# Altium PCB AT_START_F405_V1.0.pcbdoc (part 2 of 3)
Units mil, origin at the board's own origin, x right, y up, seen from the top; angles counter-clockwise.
Board outline 15424.54 x 3535.36 mil, 2 copper layers (Top Layer, Bottom Layer); 147 components, 139 nets, 556 pads, 794 vias.
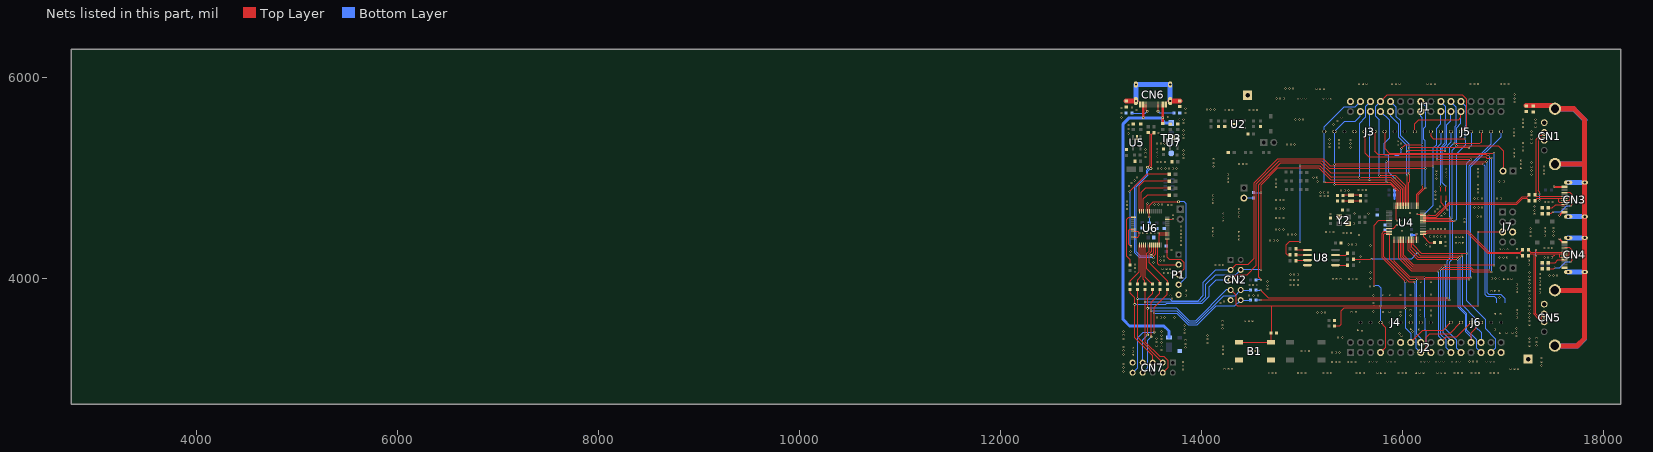
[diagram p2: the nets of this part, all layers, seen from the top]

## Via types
v1: diameter 19.68, hole 11.81, Top Layer to Bottom Layer, 688 vias
v2: diameter 19.69, hole 11.81, Top Layer to Bottom Layer, 42 vias
v3: diameter 19.7, hole 11.81, Top Layer to Bottom Layer, 30 vias
v4: diameter 23.62, hole 11.81, Top Layer to Bottom Layer, 17 vias
v5: diameter 27.56, hole 13.78, Top Layer to Bottom Layer, 15 vias
v6: diameter 27.56, hole 15.75, Top Layer to Bottom Layer, 2 vias

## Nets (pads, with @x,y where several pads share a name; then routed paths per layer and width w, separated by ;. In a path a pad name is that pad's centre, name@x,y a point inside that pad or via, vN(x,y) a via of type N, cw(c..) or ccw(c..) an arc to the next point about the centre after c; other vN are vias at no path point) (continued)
$4N333: C24.2 R23.2 Y1.2 | length 173.4
  Top Layer w6: C24.2@15411.08,4772.56 15412.08,4773.56 R23.2@15584.08,4773.56
$4N335: C23.2 R22.2 Y1.1 | length 171
  Top Layer w6: C23.2@15411.08,4831.56 Y1.1@15487.58,4831.56 R22.2@15582.08,4831.56
$4N462: JP1.2 R31.1 | length 95.9
  Bottom Layer w6: JP1.2@14423.65,4803.5 R31.1@14519.52,4803.5
ATLINK_5V: CN6.A4B9 CN6.B4A9 D3.2 F2.1 TP3.1 | length 3381.4
  Top Layer w25: v5(13421.92,5603.02) 13422.08,5603.17 CN6.B4A9@13422.08,5734.27 ; v5(13614.56,5603.02) v5@13615.03,5603.49 ; CN6.A4B9@13615.08,5734.27 13615.08,5603.49 13615.08,5548.73 F2.1@13616.58,5547.23
  Bottom Layer w30: D3.2@13676.62,3414.32 13676.58,3481.57 13626.58,3531.57 13283.81,3531.57 13220.92,3594.45 13220.92,5542.59 13281.34,5603.02 v5(13421.92,5603.02) v5(13614.56,5603.02) 13614.56,5572.39 13636.92,5550.02 TP3.1@13699.92,5550.02
ATLK_RX: CN2.10 CN7.10 R10.2 R48.1 | length 2143.2
  Top Layer w6: v4(13530.58,3469.57) v2(13530.58,3659.57) 13530.58,3717.57 13660.58,3847.57 R48.1@13660.58,3892.07
  Bottom Layer w6: CN7.10@13315.34,3066.01 13365.92,3116.59 13365.92,3415.01 13420.47,3469.57 v4(13530.58,3469.57) ; v2(13530.58,3659.57) 13752.58,3659.57 13868.58,3543.57 13960.58,3543.57 14148.58,3731.57 14333.65,3731.57 CN2.10@14390.92,3788.84 ; CN2.10@14390.97,3788.89 14391.26,3789.2 R10.2@14490.52,3789.2
ATLK_TX: CN2.8 CN7.8 R9.2 R47.1 | length 2063.7
  Top Layer w6: v4(13499.34,3422.01) 13499.34,3768.34 13586.34,3855.34 R47.1@13586.34,3885.01
  Bottom Layer w6: CN7.8@13415.35,3066.01 13463.92,3114.58 13463.92,3386.58 v4(13499.34,3422.01) ; v4(13498.58,3681.57) 13756.58,3681.57 13876.58,3561.57 13950.58,3561.57 14222.58,3833.57 14335.65,3833.57 CN2.8@14390.92,3888.84 14392.02,3887.74 R9.2@14486.73,3887.74
BOOT0/PF11: CN2.4 CN7.4 J1.28 R31.2 R45.1 U4.60 | length 5639.3
  Top Layer w6: R45.1@13438.34,3887.01 13438.34,3375.8 13583.12,3231.01 13623.92,3231.01 13665.92,3189.01 13665.92,3116.59 CN7.4@13615.34,3066.01 ; v2@14594.52,4089.62 v3(14594.52,4858.5) 14594.52,4937.51 14760.58,5103.56 15169.95,5103.56 15287.95,4985.56 v1(15675.45,4985.56) 15884.58,4985.56 15982.45,4887.69 U4.60@15982.45,4727.85
  Bottom Layer w6: v4(13438.58,3769.57) 13994.58,3769.57 14044.58,3819.57 14044.58,3944.57 14141.58,4041.57 14343.65,4041.57 CN2.4@14390.92,4088.84 14391.65,4089.57 v2(14594.58,4089.57) ; R31.2@14513.52,4858.5 v3(14594.52,4858.5) ; v1(15675.45,4985.56) 15675.58,4985.82 15675.58,5656.99 J1.28@15683.44,5664.86
CC1: CN6.A5 R56.1 | length 231.5
  Top Layer w6: v5@13567.58,5668.56 v5(13567.77,5668.77) CN6.A5@13567.77,5734.27
  Bottom Layer w6: v5(13567.77,5668.77) 13585.98,5650.56 R56.1@13725.92,5650.56
CC2: CN6.B5 R57.1 | length 230.4
  Top Layer w6: CN6.B5@13449.67,5734.27 13449.67,5680.47 v5(13461.58,5668.56)
  Bottom Layer w6: R57.1@13309.24,5650.56 13443.58,5650.56 v5(13461.58,5668.56)
CS: R60.2 U8.1 | length 119.5
  Top Layer w6: R60.2@14941.52,4299 14953.52,4287 U8.1@15056.06,4287
EGND: C30.2 CN1.SH1 CN1.SH2 CN3.13 CN3.14 CN3.15 CN3.16 CN4.13 CN4.14 CN4.15 CN4.16 CN5.SH1 CN5.SH2 R59.1 | length 7841
  Top Layer w50: C30.2@17233.58,5723.56 17489.51,5723.56 CN1.SH1@17519.93,5693.15 17706.99,5693.15 17815.88,5584.27 17815.88,5146.56 ; CN5.SH2@17518.93,3334.97 17522.33,3331.57 17738.58,3331.57 17815.88,3408.86 17815.88,3885.08 ; CN5.SH1@17518.93,3886.15 17814.8,3886.15 17815.88,3885.08 ; CN1.SH2@17519.93,5141.97 17811.28,5141.97 17815.88,5146.56 ; 17815.88,3885.08 CN4.15@17815.88,4068.47 CN4.16@17815.88,4408.66 CN3.15@17815.88,4618.47 CN3.16@17815.88,4958.66 17815.88,5146.56
  Bottom Layer w50: CN5.SH2@17518.93,3334.97 17520.33,3333.57 17745.58,3333.57 17815.88,3403.86 17815.88,3884.97 ; CN5.SH1@17518.93,3886.15 17814.69,3886.15 17815.88,3884.97 ; CN1.SH2@17519.93,5141.97 17812.82,5141.97 17815.88,5138.92 ; CN1.SH1@17519.93,5693.15 17703.99,5693.15 17816.58,5580.56 17815.88,5579.86 17815.88,5138.92 ; CN4.13@17651.28,4068.47 CN4.15@17815.88,4068.47 ; CN4.14@17651.28,4408.66 CN4.16@17815.88,4408.66 ; CN3.13@17651.28,4618.47 CN3.15@17815.88,4618.47 ; CN3.14@17651.28,4958.66 CN3.16@17815.88,4958.66 ; 17815.88,3884.97 CN4.15@17815.88,4068.47 ; CN4.15@17815.88,4068.47 CN4.16@17815.88,4408.66 ; CN4.16@17815.88,4408.66 CN3.15@17815.88,4618.47 ; CN3.15@17815.88,4618.47 CN3.16@17815.88,4958.66 ; CN3.16@17815.88,4958.66 17815.88,5138.92
EGND2: C29.2 CN6.13 CN6.14 CN6.15 CN6.16 R55.1 | length 863.4
  Top Layer w50: R55.1@13250.58,5770.56 13348.17,5770.56 CN6.14@13348.48,5770.27 ; CN6.13@13688.67,5770.27 13688.82,5770.12 C29.2@13784.58,5770.12
  Bottom Layer w50: CN6.14@13348.48,5770.27 CN6.16@13348.48,5934.86 CN6.15@13688.67,5934.86 CN6.13@13688.67,5770.27
FCC1: CN3.A5 R17.1 | length 176.6
  Top Layer w6: R17.1@17452.24,4706.56 17494.58,4706.56 17527.38,4739.36 CN3.A5@17615.28,4739.36
FCC2: CN3.B5 R16.1 | length 457.9
  Top Layer w6: R16.1@17453.24,4646.56 17478.58,4646.56 v1(17499.58,4667.56) ; CN3.B5@17615.28,4857.47 17669.67,4857.47 17692.58,4834.56 17692.58,4742.56 v1(17675.58,4725.56)
  Bottom Layer w6: v1(17499.58,4667.56) 17576.58,4667.56 17634.58,4725.56 v1(17675.58,4725.56)
FD+: CN1.3 CN3.A6 CN3.B6 R18.2 | length 1102.9
  Top Layer w11.2: R18.2@17321.58,4833.56 R18.2@17321.4,4833.4 ; CN1.3@17413.22,5456.93 17382.46,5426.16 17369.73,5426.16 17334.38,5390.81 17334.38,4850.36 R18.2@17321.58,4837.56 17321.4,4837.4 R18.2@17321.4,4833.4 ; CN3.A6@17615.28,4778.77 17658.78,4778.77 17666.58,4786.56 17666.58,4809.56 17658.08,4818.06 CN3.B6@17615.28,4818.06 17579.12,4818.06 17577.88,4816.81 17337.99,4816.81 R18.2@17321.4,4833.4
FD-: CN1.2 CN3.A7 CN3.B7 R19.2 | length 1109.5
  Top Layer w11.2: R19.2@17321.24,4774.56 17321.24,4781.87 17338.98,4799.61 17367.52,4799.61 ; v1(17367.52,4779.62) 17367.52,4799.61 ; v1(17367.58,4843.56) 17367.58,4861.56 17351.58,4877.56 17351.58,5383.68 17369.16,5401.27 17390.15,5401.27 CN1.2@17413.22,5378.19 ; 17559.58,4799.5 17559.58,4767.56 17568.08,4759.06 CN3.B7@17615.28,4759.06 ; CN3.A7@17615.28,4798.36 17579.12,4798.36 17577.88,4799.61 17367.52,4799.61
  Bottom Layer w11.2: v1(17367.52,4779.62) v1@17367.52,4843.51
GND: B1.3 B1.4 C1.2 C2.2 C3.2 C4.2 C5.2 C6.2 C7.2 C8.2 C9.2 C10.2 C11.2 C12.2 C13.1 C14.2 C15.2 C16.2 C17.2 C18.2 C19.2 C20.1 C22.2 C23.1 C24.1 C25.1 C26.1 C27.1 C28.1 C29.1 C30.1 CN1.4 CN2.9 CN3.A1B12 CN3.B1A12 CN4.A1B12 CN4.B1A12 CN5.4 CN6.A1B12 CN6.B1A12 CN7.9 D4.2 J1.31 J2.12 J2.31 J3.7 J4.6 J4.7 J7.6 LED1.2 P1.5 R2.1 R7.2 R16.2 R17.2 R20.2 R40.2 R42.2 R49.2 R51.2 R55.2 R56.2 R57.2 R59.2 T1.1 T2.1 TP3.4 U2.2 U4.12 U4.31 U4.63 U5.2 U6.8 U6.20 U6.23 U6.35 U6.39 U6.40 U6.47 U7.2 U8.4 Y2.2 Y2.4 | length 1299.9
  Top Layer w6: v1(17488.04,4212.56) 17510.36,4234.88 17518.46,4234.89
  Top Layer w8: U4.12@15868.28,4503.44 15913.45,4503.44 v1(15946.58,4536.56) ; U4.63@15935.22,4727.85 15935.22,4593.93 v1(15946.58,4582.56) ; v1(16139.58,4445.56) 16139.93,4445.2 U4.31@16139.93,4389.27
  Top Layer w10: U6.23@13324.5,4416.1 13365.11,4416.1 13383.58,4434.56 v1(13383.58,4457.56) 13365.98,4475.16 U6.20@13324.5,4475.16 ; U6.8@13462.3,4672.02 13462.58,4672.3 v1(13462.58,4749.56) ; U6.35@13580.41,4337.36 13580.41,4448.2 ; U6.39@13659.15,4435.8 13592.81,4435.8 13580.41,4448.2 ; U6.40@13659.15,4455.48 13659.06,4455.56 v1(13573.04,4455.56) 13580.41,4448.2 ; U6.47@13659.15,4593.27 13717.28,4593.27 v1(13717.58,4593.56)
  Top Layer w20: v1(17508.58,4919.56) 17513.58,4914.56 17614.47,4914.56 CN3.B1A12@17615.28,4915.36 ; v1(17562.58,4398.56) 17595.78,4365.36 CN4.B1A12@17615.28,4365.36 ; v1(17564.58,4632.56) 17593.58,4661.56 CN3.A1B12@17615.28,4661.56
  Bottom Layer w20: C4.2@15924.08,4883.56 15924.58,4883.06 C5.2@15924.58,4833.56 15924.58,4796.56 ; C6.2@16091.58,4434.06 16128.08,4434.06 v1(16139.58,4445.56)
  other v1: 14670.58,3063.57 14707.81,3063.57 14745.04,3063.57 14960.58,3063.57 14997.81,3063.57 15035.04,3063.57 15217.58,3063.57 15254.81,3063.57 15292.04,3063.57 15542.58,3063.57 15579.81,3063.57 15617.04,3063.57 15962.58,3063.57 15999.81,3063.57 16037.04,3063.57 16518.58,3063.57 16555.81,3063.57 16593.04,3063.57 16689.58,3063.57 16726.81,3063.57 16764.04,3063.57 16876.58,3063.57 16913.81,3063.57 16951.04,3063.57 15752.58,3064.57 15789.81,3064.57 15827.04,3064.57 16134.58,3064.57 16171.81,3064.57 16209.04,3064.57 16350.58,3064.57 16387.81,3064.57 16425.04,3064.57 13225.58,3078.57 13817.58,3097.57 14230.58,3100.57 14267.81,3100.57 14305.04,3100.57 17077.58,3104.57 17114.81,3104.57 17152.04,3104.57 13225.58,3115.8 13817.58,3134.8 17387.58,3136.57 13225.58,3153.03 13817.58,3172.03 15300.58,3173.57 15337.81,3173.57 15375.04,3173.57 15457.58,3173.57 15494.81,3173.57 15532.04,3173.57 17387.58,3173.8 15666.58,3174.57 15703.81,3174.57 15741.04,3174.57 15851.58,3174.57 15888.81,3174.57 15926.04,3174.57 16185.58,3174.57 16222.81,3174.57 16260.04,3174.57 16334.58,3174.57 16371.81,3174.57 16409.04,3174.57 16495.58,3174.57 16532.81,3174.57 16570.04,3174.57 16838.58,3174.57 16875.81,3174.57 16913.04,3174.57 16667.58,3175.57 16704.81,3175.57 16742.04,3175.57 17387.58,3211.03 13317.58,3239.57 13224.58,3247.57 14213.58,3252.57 15300.58,3267.57 15337.81,3267.57 15375.04,3267.57 13317.58,3276.8 14494.29,3280.57 14531.52,3280.57 14568.75,3280.57 14996.57,3280.56 15033.8,3280.56 15071.04,3280.56 13224.58,3284.8 14213.58,3289.8 13601.58,3291.57 13317.58,3314.03 13840.58,3314.57 13224.58,3322.03 14213.58,3327.03 13601.58,3328.8 13553.58,3333.57 17268.58,3333.57 17336.58,3334.57 13840.58,3351.8 14059.58,3362.57 13601.58,3366.03 13553.58,3370.8 17268.58,3370.8 17336.58,3371.8 13840.58,3389.03 14059.58,3399.8 13601.58,3400.57 13224.58,3401.57 13553.58,3408.03 17268.58,3408.03 17336.58,3409.03 15360.58,3416.57 15406.97,3416.57 17138.58,3429.57 15992.58,3432.57 14059.58,3437.03 13601.58,3437.8 13224.58,3438.8 15971.58,3454.57 13829.58,3459.57 16974.58,3462.57 17036.92,3462.57 17098.36,3462.57 17138.58,3466.8 13601.58,3475.03 13224.58,3476.03 16100.58,3476.57 15597.58,3478.57 15560.58,3492.57 16920.58,3496.35 13829.58,3496.8 16168.58,3497.57 16088.58,3502.57 14210.58,3503.57 17138.58,3504.03 13829.58,3534.03 14210.58,3540.8 17268.58,3542.1 14210.58,3578.03 17268.58,3579.33 14436.58,3582.57 14473.81,3582.57 14511.04,3582.57 13559.11,3615.57 13596.34,3615.57 13633.58,3615.57 13731.58,3616.57 17139.58,3616.57 17268.58,3616.57 15981.58,3633.57 16285.58,3634.57 16081.58,3635.57 16178.58,3635.57 16920.58,3647.57 16975.48,3647.57 17139.58,3653.8 17267.58,3655.1 15156.58,3663.57 15193.81,3663.57 15231.04,3663.57 15495.58,3667.57 15540.58,3667.57 15807.58,3670.57 15981.58,3671.25 15873.58,3671.57 15715.58,3673.92 16285.58,3685.21 16081.58,3687.73 16178.58,3688.83 17139.58,3691.03 17267.58,3692.33 17267.58,3729.57 15715.58,3759.57 14191.58,3760.57 17267.58,3767.1 14223.58,3773.57 17267.58,3804.33 13707.58,3806.57 15715.58,3833.08 13844.58,3833.9 14474.58,3835.57 14517.81,3835.57 14562.28,3835.57 16178.58,3835.71 13693.58,3836.57 15809.58,3836.57 15879.58,3836.57 15982.58,3837.57 16079.58,3837.57 17267.58,3841.57 16285.58,3846.13 17368.58,3863.1 17139.58,3867.57 16887.58,3876.57 16924.81,3876.57 16962.04,3876.57 17267.58,3878.1 13844.58,3885.57 14656.58,3898.57 17368.58,3900.33 17139.58,3904.8 17267.58,3915.33 15679.52,3922 14656.58,3935.8 17368.58,3937.57 14476.58,3938.57 14513.81,3938.57 14551.04,3938.57 14886.58,3938.57 14923.81,3938.57 14961.04,3938.57 17139.58,3942.03 17267.58,3952.57 16183.58,3970.57 16286.58,3970.57 17368.58,3972.1 14656.58,3973.03 17267.58,3987.57 14885.58,3988.57 14922.81,3988.57 14960.04,3988.57 15309.58,3996.57 15346.81,3996.57 15384.04,3996.57 15469.58,3998.57 15506.81,3998.57 15544.04,3998.57 17014.11,4000.57 17051.34,4000.57 17088.58,4000.57 15683.52,4003 16890.58,4002.57 16927.81,4002.57 16965.04,4002.57 17368.58,4009.33 17267.58,4024.8 17466.58,4034.57 17503.81,4034.57 17541.04,4034.57 14885.58,4044.57 14922.81,4044.57 14960.04,4044.57 17368.58,4046.57 13630.11,4058.57 13667.34,4058.57 13704.58,4058.57 17267.58,4062.03 15683.52,4064 13339.58,4070.57 13613.11,4099.56 13650.34,4099.56 13687.58,4099.56 13339.58,4107.8 14142.58,4136.56 14179.81,4136.56 14217.04,4136.56 17259.58,4143.56 13339.58,4145.03 13524.58,4163.56 15580.52,4165 17259.58,4180.8 13593.58,4182.56 13627.58,4182.56 17413.58,4212.56 17450.81,4212.56 16969.58,4214.56 17006.81,4214.56 17044.04,4214.56 17142.58,4214.56 13593.58,4219.8 13627.58,4220.63 15581.52,4224 13294.58,4236.56 13294.58,4271.69 13703.58,4288.56 16970.58,4294.56 17007.81,4294.56 17045.04,4294.56 17142.58,4295.56 17417.58,4306.94 17454.81,4306.94 17492.04,4306.94 16276.52,4324 16429.58,4325.56 15684.52,4331 13797.58,4337.56 15462.52,4341 15499.75,4341 15536.98,4341 16242.52,4342 16533.52,4355 16569.02,4355 16606.25,4355 16429.58,4368.17 13797.58,4374.8 14683.52,4383 14720.75,4383 14757.98,4383 14376.58,4389.56 13797.58,4412.03 16533.52,4418 16569.02,4418 16606.25,4418 16277.58,4420.56 16314.81,4420.56 16352.04,4420.56 16387.54,4420.56 16424.77,4420.56 14376.58,4426.8 17274.58,4427.56 14117.58,4431.56 17418.58,4431.56 17505.58,4432.56 14863.52,4442 14900.75,4442 14937.98,4442 13796.58,4445.56 13498.58,4455.56 13535.81,4455.56 15414.58,4455.56 15451.81,4455.56 15489.04,4455.56 13420.81,4457.56 13458.04,4457.56 14376.58,4464.03 17274.58,4464.8 15240.58,4467.56 15277.81,4467.56 15315.04,4467.56 14117.58,4468.8 17418.58,4468.8 17505.58,4469.8 13796.58,4482.8 14742.52,4491 14779.75,4491 14816.98,4491 16279.58,4497.56 16316.81,4497.56 16354.04,4497.56 16386.58,4497.56 16423.81,4497.56 17274.58,4502.03 14117.58,4506.03 17418.58,4506.03 17505.58,4507.03 13796.58,4520.03 15983.81,4536.56 15517.52,4550 14217.58,4573.56 15983.81,4582.56 16078.52,4596 14742.52,4607 14779.75,4607 14816.98,4607 14217.58,4610.8 14376.58,4621.56 16392.58,4623.56 13717.58,4637.57 15284.52,4644 17317.58,4643.56 14217.58,4648.03 16419.58,4650.56 16076.52,4654 14376.58,4658.8 16326.58,4669.56 17317.58,4680.8 14376.58,4696.03 13259.58,4696.56 16350.58,4696.56 14743.52,4699 14780.75,4699 14817.98,4699 16719.11,4708.56 16756.34,4708.56 16793.58,4708.56 17317.58,4718.03 16375.58,4721.56 13259.58,4733.8 13668.58,4734.56 13703.67,4734.56 13534.58,4740.56 13571.81,4740.56 13609.04,4740.56 14117.58,4753.56 17418.58,4763.56 17455.81,4763.56 17493.04,4763.56 13259.58,4771.03 14743.52,4785 14780.75,4785 14817.98,4785 14117.58,4790.8 16332.58,4796.56 16718.58,4798.56 16755.81,4798.56 16793.04,4798.56 16943.58,4798.56 16980.81,4798.56 15186.58,4824.56 15223.81,4824.56 15261.04,4824.56 14117.58,4828.03 16332.58,4833.8 16753.58,4857.56 15185.58,4858.56 15222.81,4858.56 15260.04,4858.56 16332.58,4871.03 15390.58,4880.56 15427.81,4880.56 15465.04,4880.56 15564.58,4884.56 15601.81,4884.56 15639.04,4884.56 16753.58,4894.8 14741.58,4913.56 13278.58,4925.56 16753.58,4932.03 14741.58,4950.8 13305.58,4952.56 14262.58,4963.56 15153.52,4969 13332.58,4978.56 14741.58,4988.03 14262.58,5000.8 16342.58,5000.56 13357.58,5006.56 15115.58,5010.56 15152.81,5010.56 16437.58,5019.56 16753.58,5019.56 14262.58,5038.03 16342.58,5037.8 17286.58,5040.56 17410.58,5041.56 16437.58,5056.8 16753.58,5056.8 16342.58,5075.03 17286.58,5077.8 17410.58,5078.8 16437.58,5094.03 16753.58,5094.03 13567.58,5098.56 13604.81,5098.56 13642.04,5098.56 13678.58,5098.56 13715.81,5098.56 13753.04,5098.56 17183.58,5105.56 17286.58,5115.03 17410.58,5116.03 14118.58,5116.56 14375.58,5142.56 14412.81,5142.56 14450.04,5142.56 17183.58,5142.8 14118.58,5153.8 17286.58,5159.56 13562.58,5162.56 13599.81,5162.56 13637.04,5162.56 17183.58,5180.03 14118.58,5191.03 13821.58,5201.56 13444.58,5213.56 17109.58,5215.56 13560.58,5218.56 13821.58,5238.8 13444.58,5250.8 17109.58,5252.8 13560.58,5255.8 13821.58,5276.03 17201.58,5277.56 13444.58,5288.03 17109.58,5290.03 13560.58,5293.03 15370.58,5308.56 15483.58,5308.56 15276.58,5311.56 17201.58,5314.8 15959.58,5333.56 14853.58,5337.56 14890.81,5337.56 14928.04,5337.56 15370.58,5345.8 15483.58,5345.8 15987.58,5346.56 13559.58,5347.56 13596.81,5347.56 13634.04,5347.56 15276.58,5348.8 17201.58,5352.03 17286.58,5354.03 15959.58,5374.29 15370.58,5383.03 15483.58,5383.03 15276.58,5386.03 17286.58,5393.56 13820.58,5401.56 17110.58,5419.56 17286.58,5430.8 13820.58,5438.8 13272.58,5445.56 13572.58,5450.56 17110.58,5456.8 17286.58,5468.03 13820.58,5476.03 13272.58,5490.09 17110.58,5494.03 17202.58,5512.56 17324.58,5513.56 13272.19,5532.35 15313.58,5536.56 17202.58,5549.8 13821.58,5550.56 17324.58,5550.8 15356.58,5570.56 14938.58,5586.56 14975.81,5586.56 15013.04,5586.56 17202.58,5587.03 13779.58,5587.56 13821.58,5587.8 17324.58,5588.03 15395.58,5603.56 13204.58,5604.56 13669.58,5610.56 13840.57,5650.57 13204.58,5651.69 14480.58,5679.56 14517.81,5679.56 14555.04,5679.56 13355.58,5680.56 14237.58,5681.56 14274.81,5681.56 14312.04,5681.56 14054.58,5685.56 14091.81,5685.56 14129.04,5685.56 13840.57,5697.23 13203.58,5700.56 13309.79,5705.25 17114.58,5759.56 14960.58,5792.56 14997.81,5792.56 15035.04,5792.56 15217.58,5792.56 15254.81,5792.56 15292.04,5792.56 14745.58,5794.56 14782.81,5794.56 14820.04,5794.56 17114.58,5796.8 17114.58,5834.03 15144.58,5891.56 15181.81,5891.56 15219.04,5891.56 14838.58,5894.56 14875.81,5894.56 14913.04,5894.56 16680.58,5939.56 16717.81,5939.56 16755.04,5939.56 16980.58,5939.56 17017.81,5939.56 17055.04,5939.56 15569.58,5941.56 15606.81,5941.56 15644.04,5941.56 15898.58,5941.56 15935.81,5941.56 15973.04,5941.56 16249.58,5941.56 16286.81,5941.56 16324.04,5941.56
  other v3: 16967.52,3815 15568.52,4437 15996.52,4474 16078.52,4547 16619.52,4566 16619.52,4594 16746.52,4620 16783.21,4620 15522.52,4648 15663.52,4652 16969.52,4970 17010.38,4970
HCC1: CN4.A5 R20.1 | length 174
  Top Layer w6: R20.1@17453.24,4160.56 17520.58,4160.56 17549.38,4189.36 CN4.A5@17615.28,4189.36
HCC2: CN4.B5 R40.1 | length 459.6
  Top Layer w6: R40.1@17452.58,4100.56 17507.58,4100.56 v1(17517.58,4110.56) ; CN4.B5@17615.28,4307.47 17667.67,4307.47 17691.58,4283.56 17691.58,4183.56 17675.58,4167.56 v1(17673.58,4167.56)
  Bottom Layer w6: v1(17517.58,4110.56) 17569.58,4110.56 17626.58,4167.56 v1(17673.58,4167.56)
HD+: CN4.A6 CN4.B6 CN5.3 R21.2 | length 1239
  Top Layer w11.16: 17518.45,4266.65 CN4.B6@17595.58,4266.65 ; CN4.A6@17615.28,4228.77 17653.78,4228.77 17662.58,4237.56 17662.58,4258.56 17653.08,4268.06 CN4.B6@17615.28,4268.06
  Top Layer w11.2: R21.2@17255.58,4287.56 17276.48,4266.66 17518.45,4266.65 ; v1(17330.58,4225.56) 17323.58,4218.56 17323.58,3657.57 17361.98,3619.16 17381.46,3619.16 CN5.3@17412.22,3649.93 ; v1(17330.58,4285.56) 17330.58,4266.87 17330.77,4266.67
  Bottom Layer w11.2: v1(17330.58,4225.56) v1(17330.58,4285.56)
HD-: CN4.A7 CN4.B7 CN5.2 R30.2 | length 1169.1
  Top Layer w11.16: 17518.45,4249.48 CN4.A7@17595.58,4249.48 ; 17568.58,4249.42 17568.58,4216.56 17576.08,4209.06 CN4.B7@17615.28,4209.06
  Top Layer w11.2: R30.2@17255.58,4228.56 17276.48,4249.47 17306.57,4249.47 ; CN5.2@17412.22,3571.19 17381.46,3601.96 17354.85,3601.96 17306.38,3650.44 17306.38,4249.27 17306.57,4249.47 ; 17518.45,4249.48 17306.57,4249.47
IO0: R61.2 U8.5 | length 76.4
  Top Layer w6: 15378.52,4135 15453.52,4135 R61.2@15454.52,4136
IO1: R62.2 U8.2 | length 115.4
  Top Layer w6: R62.2@14941.52,4239 14943.52,4237 U8.2@15056.06,4237
IO2: R63.2 U8.3 | length 117.4
  Top Layer w6: R63.2@14941.52,4180 14948.52,4187 U8.3@15056.06,4187
IO3: R64.2 U8.7 | length 127
  Top Layer w6: U8.7@15334.98,4237 15436.52,4237 R64.2@15454.52,4255
LD1: LD1.2 U6.10 | length 397.2
  Top Layer w6: U6.10@13422.92,4672.02 13422.92,4794.91 13460.58,4832.56 LD1.2@13681.62,4832.56
LD2: LD2.2 U6.11 | length 485.7
  Top Layer w6: U6.11@13403.24,4672.02 13403.24,4863.23 13442.17,4902.16 LD2.2@13681.62,4902.16
LD3: LD3.2 U6.12 | length 585.9
  Top Layer w6: U6.12@13383.56,4672.02 13383.56,4927.55 13427.58,4971.56 LD3.2@13681.42,4971.56 ; LD3.2@13681.62,4971.76 LD3.2@13681.42,4971.56 ; LD3.2@13695.42,4971.56 LD3.2@13681.42,4971.56
LD4: LD4.2 U6.19 | length 1244
  Top Layer w6: v1(13286.58,4871.56) 13456.37,5041.36 LD4.2@13681.62,5041.36 ; v4(13298.92,4323.02) 13275.92,4346.02 13275.92,4486.02 13284.76,4494.85 U6.19@13324.5,4494.85
  Bottom Layer w6: v1(13286.58,4871.56) 13286.34,4871.34 13286.34,4335.6 v4(13298.92,4323.02)
M-ATLK_RX: R48.2 U6.31 | length 479.5
  Top Layer w6: U6.31@13501.67,4337.36 13501.67,4271.34 13474.58,4244.24 13474.58,4164.44 13660.34,3978.68 R48.2@13660.34,3946.01
M-ATLK_TX: R47.2 U6.30 | length 454
  Top Layer w6: U6.30@13481.98,4337.36 13481.98,4275.65 13458.58,4252.24 13458.58,4098.26 13586.34,3970.49 R47.2@13586.34,3946.01
M-NRST: C22.1 P1.4 U6.7 | length 1403.3
  Top Layer w6: v4(13480.85,4616.02) 13481.98,4617.15 U6.7@13481.98,4672.02 ; U6.7@13480.85,4673.15 U6.7@13481.98,4672.02 ; v5(13772.23,4768.02) 13521.02,4768.02 13481.98,4728.97 U6.7@13481.98,4672.02
  Bottom Layer w6: C22.1@13480.58,4557.12 13480.85,4557.4 C22.1@13480.85,4560.35 ; v4(13480.85,4616.02) C22.1@13480.85,4560.35 ; C22.1@13481.15,4560.06 C22.1@13480.85,4560.35 ; v5(13772.23,4768.02) 13827.93,4768.02 13848.93,4747.02 13848.93,4017.92 P1.4@13772.58,3941.57
M-SWCLK: P1.3 U6.37 | length 518.8
  Top Layer w6: U6.37@13659.15,4396.43 13659.15,4212.99 13682.58,4189.56 13801.58,4189.56 13829.58,4161.56 13829.58,4098.56 P1.3@13772.58,4041.57
M-SWDIO: P1.2 U6.34 | length 398.8
  Top Layer w6: U6.34@13560.72,4337.36 13560.72,4156.65 13575.8,4141.56 P1.2@13772.58,4141.56
M-USB_D+: R11.2 U6.33 | length 1619.6
  Top Layer w11.2: v5(13464.58,5110.56) 13490.48,5136.47 13490.48,5437.53 R11.2@13469.58,5458.43 ; v4(13523.58,4210.56) 13523.58,4230.19 13539.79,4246.4 13539.79,4302.9 13541.03,4304.14 U6.33@13541.03,4337.36
  Bottom Layer w11.2: v5(13464.58,5110.56) 13464.58,5089.89 13450.8,5076.11 13450.8,5038.01 13330.58,4917.79 13330.58,4265.44 13387.83,4208.19 13521.2,4208.19 v4(13523.58,4210.56)
M-USB_D-: R12.2 U6.32 | length 1549.3
  Top Layer w11.2: v5(13497.58,5098.56) 13497.58,5115.25 13507.67,5125.35 13507.67,5437.53 R12.2@13528.58,5458.43 ; v4(13499.58,4233.56) 13522.59,4256.58 13522.59,4302.9 13521.34,4304.14 U6.32@13521.34,4337.36
  Bottom Layer w11.2: v5(13497.58,5098.56) 13468,5068.99 13468,5030.88 13347.77,4910.66 13347.77,4272.56 13394.95,4225.39 13491.4,4225.39 v4(13499.58,4233.56)
M_ATLK_BOOT0: R45.2 U6.27 | length 395.7
  Top Layer w6: U6.27@13422.92,4337.36 13422.92,3998.14 13438.34,3982.72 R45.2@13438.34,3948.01
M_ATLK_NRST: R46.2 U6.28 | length 419.2
  Top Layer w6: U6.28@13442.6,4337.36 13442.6,4016.76 R46.2@13512.34,3947.01
M_ATLK_SWCLK: R41.2 U6.25 | length 427
  Top Layer w6: R41.2@13290.34,3949.01 13290.34,3978.43 13383.56,4071.64 U6.25@13383.56,4337.36
M_ATLK_SWDIO: R44.2 U6.26 | length 404.5
  Top Layer w6: R44.2@13364.34,3949.01 13364.34,3992.43 13403.24,4031.32 U6.26@13403.24,4337.36
M_ATLK_SWO: R52.2 U6.13 | length 541.5
  Top Layer w6: R52.2@13290.15,4141.98 13290.15,4191.8 13255.92,4226.02 13255.92,4592.02 13276.88,4612.97 U6.13@13324.5,4612.97
NRST: B1.1 B1.2 C13.2 CN2.7 CN7.7 J2.7 J4.3 J7.5 R46.1 U4.7 | length 7575.5
  Top Layer w6: v4(13464.58,3441.57) 13464.58,3805.57 13514.58,3855.57 13514.58,3888.24 R46.1@13512.34,3886.01 ; CN2.7@14290.92,3888.84 14340.58,3839.2 14340.58,3745.57 14356.58,3729.57 14688.08,3729.57 ; B1.1@14374.58,3367.57 B1.2@14689.58,3367.57 ; B1.2@14699.53,3365.57 14697.53,3367.57 B1.2@14689.58,3367.57 ; 15718.58,3730.62 15718.02,3730.07 ; v1(15718.58,3930.73) 15718.58,4533.56 15767.2,4582.19 U4.7@15868.28,4582.19 ; J2.7@15783.88,3267.14 15834.58,3317.84 15834.58,3514.86 J4.3@15783.86,3565.56 ; v2(16751.58,4466.56) 16998.47,4466.56 J7.5@16998.88,4466.16 ; v1@16756.08,3730.07 v1(15784.48,3730.07) 15718.02,3730.07 ; 14688.08,3729.57 14693.08,3724.57 ; 14688.08,3729.57 14693.08,3730.07 ; B1.2@14689.58,3367.57 14693.08,3371.07 C13.2@14693.08,3459.57 14693.08,3724.57 ; 14693.08,3724.57 14693.08,3730.07 ; 14693.08,3730.07 15718.02,3730.07
  Bottom Layer w6: CN7.7@13415.35,3166.01 13415.35,3392.34 v4(13464.58,3441.57) ; v4(13464.58,3705.57) 13756.58,3705.57 13884.58,3577.57 13936.58,3577.57 14247.85,3888.84 CN2.7@14290.92,3888.84 ; v1(15718.58,3930.73) 15763.65,3930.73 15784.48,3909.9 v1(15784.48,3730.07) ; v1@15783.58,3730.57 15783.86,3730.28 J4.3@15783.86,3565.56 ; v1(16750.95,3730.07) 16750.58,3730.44 16750.58,4465.56 v2(16751.58,4466.56)
OTGHS1_D+: R21.1 U4.35 | length 1083.7
  Top Layer w8: U4.35@16206.86,4471.94 16243.8,4471.94 16244.58,4472.73
  Top Layer w11.16: 16244.58,4472.73 16656.42,4472.73 16861.99,4267.15
  Top Layer w11.2: 16861.99,4267.15 16862.49,4266.65 17175.35,4266.66 R21.1@17196.26,4287.56
OTGHS1_D-: R30.1 U4.34 | length 1083.7
  Top Layer w8: U4.34@16206.86,4456.2 16243.93,4456.2 16244.58,4455.56
  Top Layer w11.16: 16244.58,4455.56 16649.31,4455.56 16853.36,4251.51
  Top Layer w11.2: 16853.36,4251.51 16855.39,4249.48 ; 16855.41,4249.47 17175.35,4249.47 R30.1@17196.26,4228.56
OTGHS1_R: R42.1 U4.33 | length 156.2
  Top Layer w8: U4.33@16206.86,4440.45 16206.86,4423.65 16268.95,4361.56 R42.1@16320.61,4361.56
PA0: J2.14 J6.1 R5.1 U4.14 | length 2623
  Top Layer w6: R5.1@15324.08,3529.57 15374.58,3529.57 15388.58,3543.57 15388.58,3677.57 15416.17,3705.16 v1(16030.58,3705.16) ; U4.14@15868.28,4471.94 15814.95,4471.94 15798.58,4455.56 15798.58,4209.56 16030.58,3977.57 v1(16030.58,3970.57) ; J2.14@16083.88,3367.14 16200.3,3483.57 16401.88,3483.57 J6.1@16483.88,3565.57
  Bottom Layer w6: v1(16030.58,3970.57) v1(16030.58,3705.16) 16030.58,3511.82 16083.88,3458.52 J2.14@16083.88,3367.14
PA1: J2.15 J6.2 U4.15 | length 2004
  Top Layer w6: U4.15@15868.28,4456.2 15824.22,4456.2 15813.58,4445.56 15813.58,4219.56 16063.58,3969.57 v1(16120.58,3969.57) ; J2.15@16183.88,3267.14 16232.58,3315.84 16232.58,3411.57 16270.58,3449.57 16467.88,3449.57 J6.2@16583.88,3565.57
  Bottom Layer w6: v1(16120.58,3969.57) 16120.58,3956.34 16125.58,3951.34 16125.58,3414.57 16134.58,3405.57 16134.58,3316.43 J2.15@16183.88,3267.14
PA2: J2.16 J5.2 U4.16 | length 3328.9
  Top Layer w6: U4.16@15868.28,4440.45 15868.28,4200.85 16075.58,3993.57 v1(16140.38,3993.57) v1(16664.58,3993.57)
  Bottom Layer w6: v1@16140.58,3993.57 16140.58,3453.57 16183.88,3410.26 J2.16@16183.88,3367.14 ; v1(16664.58,3993.57) 16664.58,5125.56 16883.88,5344.86 J5.2@16883.88,5465.56
PA3: J2.17 J5.1 U4.17 | length 3395.6
  Top Layer w6: U4.17@15919.47,4389.27 15919.47,4173.68 16078.58,4014.57 v2(16218.58,4014.57) v1(16683.78,4014.57)
  Bottom Layer w6: v2(16218.58,4014.57) 16218.58,3616.03 16224.58,3610.03 16224.58,3498.4 16234.58,3488.4 16234.58,3316.43 J2.17@16283.88,3267.14 ; v1@16683.58,4014.57 16683.58,5114.56 16983.58,5414.56 J5.1@16983.58,5465.56
PA4: J2.20 J6.3 U4.20 | length 1730
  Top Layer w6: U4.20@15966.72,4389.27 15966.72,4202.43 16094.58,4074.57 v2(16355.58,4074.57) ; J2.20@16383.88,3367.14 16438.29,3421.57 16539.88,3421.57 J6.3@16683.88,3565.57
  Bottom Layer w6: v2(16355.58,4074.57) 16355.58,3434.57 16382.58,3407.57 16382.58,3368.43 J2.20@16383.88,3367.14
PA5: J2.21 J3.6 U4.21 | length 4644.2
  Top Layer w6: J3.6@15623.88,5465.56 15623.88,5256.27 15664.58,5215.56 16828.58,5215.56 16842.58,5201.56 16887.21,5201.56 v1(16887.58,5201.93) ; U4.21@15982.45,4389.27 15982.45,4213.06 16100.95,4094.57 v2(16378.58,4094.57) 16680.58,4094.57 16708.58,4066.57 v1(16887.58,4066.57)
  Bottom Layer w6: v2(16378.58,4094.57) 16378.58,3449.57 16430.58,3397.57 16430.58,3320.43 J2.21@16483.88,3267.14 ; v1(16887.58,4066.57) v1(16887.58,5201.93)
PA6: J2.22 J3.5 U4.22 | length 4363.5
  Top Layer w6: J3.5@15723.88,5465.56 15723.88,5272.27 15762.58,5233.56 16835.76,5233.56 16843.6,5225.72 v1(16865.58,5225.72) ; U4.22@15998.2,4389.27 15998.2,4223.31 16106.95,4114.56 v2(16401.58,4114.56) 16683.58,4114.56 16710.58,4087.57 v1(16865.58,4087.57)
  Bottom Layer w6: v2(16401.58,4114.56) 16401.58,3468.57 16483.88,3386.26 J2.22@16483.88,3367.14 ; v1(16865.58,4087.57) v1(16865.58,5225.72)
PA7: J2.23 J3.4 U4.23 | length 4417.9
  Top Layer w6: J3.4@15823.88,5465.56 15823.88,5298.27 15871.58,5250.56 v1(16911.58,5250.56) ; U4.23@16013.95,4389.27 16013.95,4234.56 16114.95,4133.56 v2(16425.58,4133.56) v1(16911.58,4133.56)
  Bottom Layer w6: v2(16425.58,4133.56) 16425.58,3502.72 16534.58,3393.72 16534.58,3316.43 J2.23@16583.88,3267.14 ; v1(16911.58,4133.56) v1(16911.58,5250.56)
PA8: J1.9 J5.8 U4.41 | length 1973.9
  Top Layer w6: U4.41@16206.86,4566.44 16511.45,4566.44 v2(16521.58,4576.56) ; J5.8@16283.88,5465.56 16283.88,5422.27 16314.58,5391.56 v2(16626.58,5391.56)
  Bottom Layer w6: v2(16521.58,4576.56) 16540.58,4595.56 16540.58,5243.56 16626.58,5329.56 v2(16626.58,5391.56) 16626.58,5520.05 16634.58,5528.05 16634.58,5713.73 J1.9@16583.44,5764.86
PA9: J1.10 J3.1 JP2.2 R10.1 U4.42 | length 5450.2
  Top Layer w6: v1(14589.38,3789.76) v1(16471.38,3789.76) ; J3.1@16123.88,5465.56 16123.88,5544.86 16162.58,5583.56 16560.58,5583.56 16583.44,5606.44 J1.10@16583.44,5664.86 ; U4.42@16206.86,4582.19 16487.2,4582.19 v2(16496.58,4591.56) ; v1(16540.58,5325.56) 16953.58,5325.56 17003.58,5275.56 JP2.2@17003.58,5072.56
  Bottom Layer w6: R10.1@14545.77,3789.76 v1(14589.38,3789.76) ; v1(16471.38,3789.76) 16471.58,3789.97 16471.58,4168.56 16496.58,4193.56 v2(16496.58,4591.56) 16496.58,5281.56 v1(16540.58,5325.56) 16540.58,5503.56 16583.44,5546.44 J1.10@16583.44,5664.86
PA10: J1.11 J5.3 R9.1 U4.43 | length 4601.9
  Top Layer w6: v1(14589.38,3887.76) 14668.58,3808.57 v1(16449.58,3808.62) ; U4.43@16206.86,4597.94 16462.95,4597.94 v2(16474.58,4609.56) ; v2(16514.58,5347.56) 16772.58,5347.56 16783.88,5358.86 J5.3@16783.88,5465.56
  Bottom Layer w6: R9.1@14545.77,3887.76 v1(14589.38,3887.76) v1@14589.58,3887.57 ; v1(16449.58,3808.62) 16449.58,4178.56 16474.58,4203.56 v2(16474.58,4609.56) 16474.58,5307.56 v2(16514.58,5347.56) 16526.58,5359.56 16526.58,5517.44 16533.58,5524.44 16533.58,5714.73 J1.11@16483.44,5764.86
PA11: R19.1 U4.44 | length 1317.6
  Top Layer w6: 16432.03,4706.7 16432.03,4706.11 v1(16451.58,4686.56) ; v1(16433.58,4776.56) 16433.58,4826.16
  Top Layer w8: U4.44@16206.86,4613.69 16257.13,4613.69 16257.25,4613.56
  Top Layer w11.2: 16257.25,4613.56 16338.9,4613.56 16432.03,4706.7 16467.9,4742.56 17140.9,4742.56 17199.74,4801.4 17239.08,4801.4 R19.1@17261.92,4778.56
  Bottom Layer w6: v1(16433.58,4776.56) 16433.58,4704.56 v1(16451.58,4686.56)
PA11_E: J1.12 | length 844.8
  Top Layer w6: 16433.58,4870.56 v1(16433.58,4921.56)
  Bottom Layer w6: v1(16433.58,4921.56) 16397.58,4957.56 16397.58,5299.56 16442.58,5344.56 16442.58,5532.56 16483.44,5573.44 J1.12@16483.44,5664.86
PA12: R18.1 U4.45 | length 1266.9
  Top Layer w6: 16380.58,4826.56 16380.58,4760.16 16420.87,4719.86
  Top Layer w8: U4.45@16206.86,4629.43 16257.5,4629.43 16258.84,4630.77 ; 16267.19,4629.43 16268.53,4630.77
  Top Layer w11.2: 16258.84,4630.77 16268.53,4630.77 16331.77,4630.77 16420.87,4719.86 16460.78,4759.77 17133.78,4759.77 17192.61,4818.6 17243.29,4818.6 R18.1@17262.26,4837.56
PA12_E: J1.13 | length 937.4
  Top Layer w6: 16380.58,4870.97 v1(16380.58,4921.56)
  Bottom Layer w6: v1(16380.58,4921.56) 16380.58,5306.56 16426.58,5352.56 16426.58,5583.56 16434.58,5591.56 16434.58,5713.73 J1.13@16383.44,5764.86
PA13/SWDIO: CN2.3 CN7.3 J1.14 R44.1 U4.46 | length 6126.5
  Top Layer w6: R44.1@13364.34,3888.01 13364.34,3803.8 v4(13364.58,3803.57) 13364.58,3416.78 CN7.3@13615.34,3166.01 ; CN2.3@14290.92,4088.84 14343.65,4141.56 14461.08,4141.56 14520.52,4201 14520.52,4951.51 14757.01,5188 15218.14,5188 15286.58,5119.56 v2(16306.58,5119.56) ; v1(16143.97,4645.18) U4.46@16206.86,4645.18
  Bottom Layer w6: v4(13364.58,3803.57) 13682.58,3803.57 13702.58,3783.57 13966.58,3783.57 14020.58,3837.57 14020.58,3964.57 14144.85,4088.84 CN2.3@14290.92,4088.84 ; v1(16143.97,4645.18) 16219.69,4645.18 16306.58,4732.06 v2(16306.58,5119.56) 16306.58,5302.56 16340.58,5336.56 16340.58,5498.56 16383.44,5541.44 J1.14@16383.44,5664.86
PA14/SWCLK: CN2.5 CN7.5 J1.17 R41.1 U4.49 | length 5963.3
  Top Layer w6: R41.1@13290.34,3888.01 13290.34,3857.8 13336.58,3811.57 13336.58,3412.57 13515.34,3233.8 CN7.5@13515.34,3166.01 ; CN2.5@14290.92,3988.84 14297.85,3988.84 14346.58,4037.57 14450.08,4037.57 14543.52,4131 14543.52,4942.51 14771.01,5170 15204.14,5170 15276.58,5097.56 v2(16230.58,5097.56) ; U4.49@16155.68,4727.85 16155.68,4830.67 v2(16230.58,4905.56)
  Bottom Layer w6: v4(13336.58,3745.57) 13644.58,3745.57 13654.58,3755.57 14010.58,3755.57 14079.58,3824.57 14079.58,3920.57 14147.85,3988.84 CN2.5@14290.92,3988.84 ; J1.17@16183.44,5764.86 16232.58,5715.73 16232.58,5516.56 16214.58,5498.56 16214.58,5388.27 16230.58,5372.27 v2(16230.58,5097.56) v2(16230.58,4905.56)
PA15: J1.18 U4.50 | length 1306.4
  Top Layer w6: v2(15991.58,5297.56) 16030.58,5336.56 v2(16198.58,5336.56) ; U4.50@16139.93,4727.85 16139.93,4837.92 16198.58,4896.56 v2(16198.58,4931.56)
  Bottom Layer w6: 15924.58,5232.28 15963.3,5232.28 15991.58,5260.56 v2(15991.58,5297.56) ; J1.18@16183.44,5664.86 16183.44,5620.69 16198.58,5605.56 v2(16198.58,5336.56) v2(16198.58,4931.56)
PB0: J2.26 J6.4 U4.26 | length 1752.2
  Top Layer w6: U4.26@16061.19,4389.27 16061.19,4284.32 16153.95,4191.56 v2(16550.58,4191.56) ; J2.26@16683.88,3367.14 16683.88,3465.55 J6.4@16783.88,3565.57
  Bottom Layer w6: v2(16550.58,4191.56) 16550.58,3720.57 16624.58,3646.57 16624.58,3476.57 16683.88,3417.26 J2.26@16683.88,3367.14
PB1: J2.27 U4.27 | length 1654.3
  Top Layer w6: U4.27@16076.94,4389.27 16076.94,4296.57 16161.95,4211.56 v2(16570.58,4211.56)
  Bottom Layer w6: v2(16570.58,4211.56) 16570.58,3723.57 16637.58,3656.57 16637.58,3493.57 16734.58,3396.57 16734.58,3316.43 J2.27@16783.88,3267.14
PB2: J2.28 R65.1 U4.28 | length 2216.3
  Top Layer w6: R65.1@15513.84,4195.5 v3(15691.02,4195.5) ; U4.28@16092.69,4389.27 16092.69,4315.82 v3(16150.52,4258) 16176.95,4231.56 v1(16595.64,4231.56)
  Bottom Layer w6: v3(15691.02,4195.5) 16088.02,4195.5 v3(16150.52,4258) ; v1(16595.64,4231.56) 16595.58,3740.57 16727.58,3608.57 16727.58,3525.14 16783.87,3468.86 J2.28@16783.88,3367.14
PB3: J1.23 J5.4 R8.1 U4.55 | length 4517.8
  Top Layer w6: v2(14594.58,3989.57) 14565.52,4018.62 14565.52,4932.51 14785.01,5152 15190.14,5152 15291.58,5050.56 16068.58,5050.56 16068.58,4963.56 16061.19,4956.19 U4.55@16061.19,4727.85 ; v1(16068.58,5303.71) 16663.43,5303.71 v1@16663.58,5303.56
  Bottom Layer w6: R8.1@14549.73,3989.74 v2(14594.58,3989.57) ; J1.23@15883.44,5764.86 15938.58,5709.73 15938.58,5615.56 15982.58,5571.56 15982.58,5423.56 16068.58,5337.56 v1(16068.58,5303.71) v1(16068.58,5050.53) ; v1(16663.75,5303.74) 16683.88,5323.86 J5.4@16683.88,5465.56
PB4: J1.24 J5.6 U4.56 | length 1602.2
  Top Layer w6: U4.56@16045.45,4727.85 16045.45,5026.44 v2(16045.58,5026.56) ; v1(16045.58,5272.65) 16424.87,5272.65 v1(16425.52,5272)
  Bottom Layer w6: J1.24@15883.44,5664.86 15883.44,5619.69 15966.58,5536.56 15966.58,5409.56 16045.58,5330.56 v1(16045.58,5272.65) v2(16045.58,5026.56) ; v1(16425.52,5272) 16425.52,5300.69 16483.88,5359.05 J5.6@16483.88,5465.56
PB5: J1.25 J5.5 U4.57 | length 2517.8
  Top Layer w6: v1(15771.58,5030.56) 15930.58,5030.56 16029.7,4931.44 U4.57@16029.7,4727.85 ; J1.25@15783.44,5764.86 15850.15,5831.56 16596.58,5831.56 16634.58,5793.56 16634.58,5516.27 J5.5@16583.88,5465.56
  Bottom Layer w6: v1(15771.58,5030.56) 15771.58,5585.56 15732.58,5624.56 15732.58,5713.99 J1.25@15783.44,5764.86
PB6: J1.26 U4.58 | length 1098.4
  Top Layer w6: v1(15920.58,5004.56) 16013.95,4911.19 U4.58@16013.95,4727.85
  Bottom Layer w6: J1.26@15783.44,5664.86 15786.27,5664.86 15872.58,5578.56 15872.58,5405.56 15818.58,5351.56 15818.58,5240.56 15831.18,5227.96 15864.58,5227.96 15864.58,5060.56 v1(15920.58,5004.56)
PB7: J1.27 R62.1 U4.59 | length 3119.3
  Top Layer w6: R62.1@14882.2,4239 14856.52,4239 14841.52,4254 14841.52,4333 14877.03,4368.51 v3(14982.01,4368.51) ; v3(14982.52,5127) 15177.52,5127 15294.95,5009.56 v2(15575.58,5009.56) 15884.58,5009.56 15998.2,4895.94 U4.59@15998.2,4727.85
  Bottom Layer w6: v3(14982.01,4368.51) 14982.01,5126.49 v3(14982.52,5127) ; v2(15575.58,5009.56) 15575.58,5549.56 15632.58,5606.56 15632.58,5713.99 J1.27@15683.44,5764.86
PB8: J1.29 J3.10 U4.61 | length 4697.3
  Top Layer w6: v1(15224.58,4962.56) v1(15840.36,4962.56) 15881.58,4962.56 15966.72,4877.43 U4.61@15966.72,4727.85 ; v1(15840.36,5167.56) v2(16839.58,5167.56)
  Bottom Layer w6: v1(15224.58,4962.56) 15224.58,5464.86 J3.10@15223.88,5465.56 15223.88,5514.86 15422.58,5713.56 15532.15,5713.56 J1.29@15583.44,5764.86 ; v1(15840.36,4962.56) v1(15840.36,5167.56) ; v2(16839.58,5167.56) 16839.58,3866.57 16859.58,3846.57 16981.58,3846.57 17020.58,3807.57 17020.58,3763.57
PB9: J1.30 J3.9 U4.62 | length 4650.2
  Top Layer w6: v1@15323.58,5140.57 v1(16805.68,5140.57) ; v1(15323.88,4938.86) 15324.58,4939.56 15882.58,4939.56 15950.97,4871.18 U4.62@15950.97,4727.85
  Bottom Layer w6: v1(15323.88,4938.86) v1(15323.88,5140.39) J3.9@15323.88,5464.56 ; J3.9@15323.88,5465.56 15424.88,5566.56 15533.58,5566.56 15583.44,5616.44 J1.30@15583.44,5664.86 ; v1(16805.68,5140.57) 16821.58,5124.68 16821.58,3847.57 16841.58,3827.57 16913.58,3827.57 16936.58,3804.57 16936.58,3764.08
PB10: J2.29 J5.7 U4.29 | length 3326.1
  Top Layer w6: U4.29@16108.44,4389.27 16108.44,4338.07 16194.95,4251.56 v1(16642.58,4251.56) ; v1(16346.58,5188.56) v1(16681.58,5188.56)
  Bottom Layer w6: v1(16346.58,5188.56) 16346.58,5309.56 16383.88,5346.86 J5.7@16383.88,5465.56 ; v1@16680.58,5188.56 16642.58,5150.56 v1(16642.58,4251.56) 16642.58,3779.57 16828.58,3593.57 16828.58,3503.57 16932.58,3399.57 16932.58,3315.84 J2.29@16883.88,3267.14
